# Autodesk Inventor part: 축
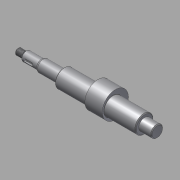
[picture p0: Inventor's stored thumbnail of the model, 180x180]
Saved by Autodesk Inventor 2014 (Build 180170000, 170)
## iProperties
Created: 2015-12
Part Number: 축
Document SubType Name: Modeling
Designer: mdu
Density: 1 g/cm^3
Material: 강철, 연강
Appearance: 강철
Author: mdu
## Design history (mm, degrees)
sketch "스케치1"
  geometry: L1 (62, 100.9)-(62, 67.1) reference; L2 (51, 101.2)-(51, 84) reference; L3 (-51, 84)-(-51, 101.2) reference; L4 (-62, 67.1)-(-62, 100.9) reference; L5 (-51.6, 91.5)-(-61.4, 91.5) reference; L6 (51.6, 91.5)-(61.4, 91.5) reference; L7 (67, 84)-(-109, 84); L8 (-77, 64.201)-(-77, 103.799) reference; L9 (67, 84)-(67, 91.5); L10 (67, 91.5)-(51, 91.5); L11 (51, 91.5)-(51, 95.5); L12 (51, 95.5)-(-51, 95.5); L13 (-51, 95.5)-(-51, 91.5); L14 (-51, 91.5)-(-79, 91.5); L15 (-79, 91.5)-(-79, 90); L16 (-79, 90)-(-99, 90); L17 (-99, 90)-(-99, 87); L18 (-100.5, 88)-(-109, 88); L19 (-109, 88)-(-109, 84); L20 (-99, 87)-(-100.5, 87); L21 (-100.5, 87)-(-100.5, 88); 2 further points
  constraints: 32 end point, 7 parallel, 6 point on line, 5 perpendicular, 2 collinear, 2 horizontal, 1 midpoint, 4 other
  dimensions: "d0" = 5 distance from line of L7.start L1; "d2" = 2 distance between parallel lines of L15 L8; "d3" = 23 diameter of L12 L7; "d4" = 12 diameter of L16 L7; "d5" = 1.5 distance of L17.end L20.end; "d6" = 6 diameter of L20 L7; "d7" = 20 distance of L15.end L16.end; "d8" = 10 distance between parallel lines of L17 L19; "d9" = 8 diameter of L18 L7
revolve "회전1" sketch "스케치1" stored, may be unused: angle "d10" = 90 deg
sketch "스케치2"
  geometry: C1 r 11.5 at (84, 0) reference; C2 r 11.5 at (84, 0) reference; C3 r 16.5 at (87, 0); 1 further point
  constraints: 1 centre point, 1 horizontal alignment
  dimensions: "d11" = 33 diameter of C3; "d12" = 3 distance of C3.centre C1.centre
extrude "돌출1" join sketch "스케치2" stored distance "d13" = 22; taper "d14" = 0 deg
chamfer "모따기1" distance "d15" = 1; stored, may be unused: second distance "d16" = 2, angle "d17" = 45 deg
feature "스레드1" dims "d18" = 10, "d19" = 0
node "작업 평면1"
sketch "스케치3"
  geometry: L1 (-5, -2)-(3, -2); L2 (3, 2)-(-5, 2); L3 (-10, -5)-(-10, 5) reference; A1 r 2 centre (3, 0) between (3, -2) and (3, 2); A2 r 2 centre (-5, 0) between (-5, 2) and (-5, -2); 2 further points
  constraints: 4 end point, 4 point on circle, 4 tangent, 2 centre point, 1 horizontal, 1 horizontal alignment, 1 midpoint, 1 parallel
  dimensions: "d20" = 4 distance between parallel lines of L1 L2; "d21" = 12 dimension on A1 A2; "d22" = 3 distance edge to line of A2 L3
extrude "돌출2" cut sketch "스케치3" distance "d23" = 2.5; taper "d24" = 0 deg
fillet "모깎기1" dims "d25" = 0.3
fillet "모깎기2" dims "d26" = 3
node "솔리드1"
node "참조1"
node "참조2"
node "참조3"
node "참조4"
node "참조5"
node "투영된 루프1"
